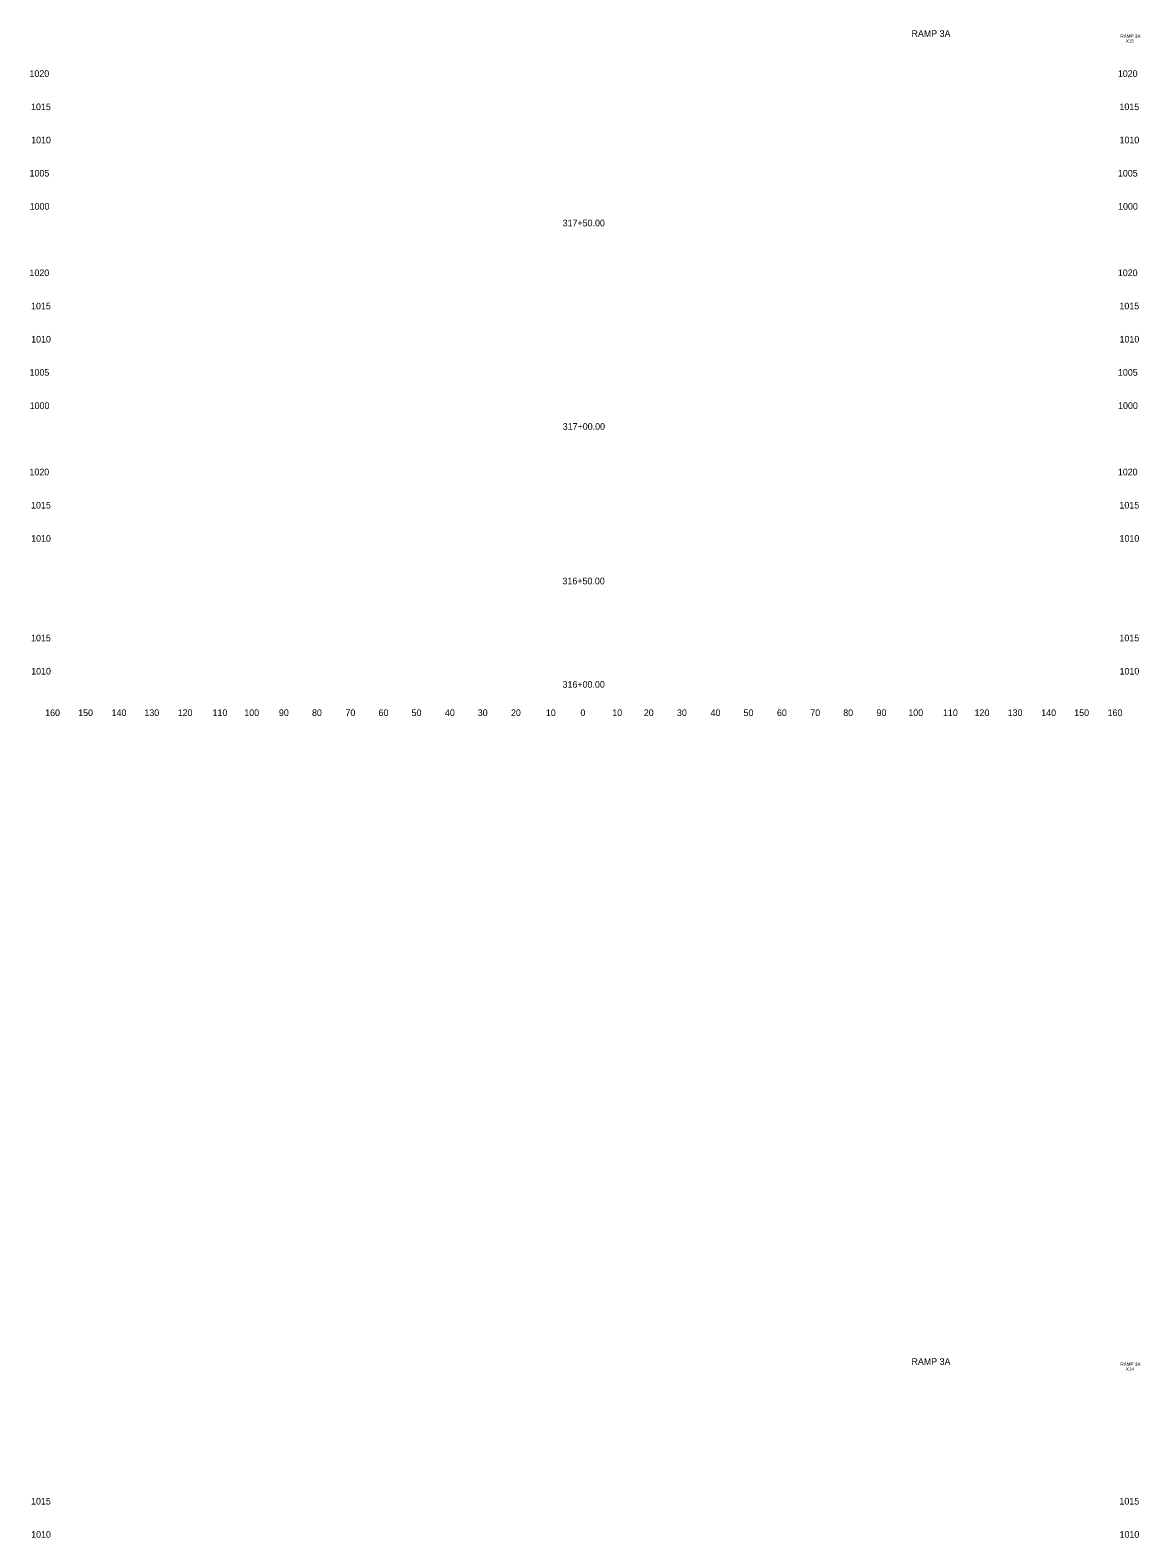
# Model space of a CAD drawing. Extents: x 4286 to 5843, y 4997 to 8804.
# Drawn here: x 5508.6 to 5842.8, y 6350 to 6804.1 of the extents above; entities that cross this region are included whole.
import ezdxf

# ---------------------------------------------------------------- set-up
doc = ezdxf.new("R2010")
doc.units = 0
for name, color, linetype in [('RD_SHT_ID', 7, 'Continuous'), ('RD_XS_TX_Offset', 7, 'Continuous'), ('RD_XS_TX_Station', 7, 'Continuous')]:
    doc.layers.add(name, color=color, linetype=linetype)

msp = doc.modelspace()

# ---------------------------------------------------------------- texts
at = {"layer": 'RD_SHT_ID'}
for s, height, p in [('RAMP 3A', 2, (5774.02, 6802.06)), ('RAMP 3A', 1, (5836.93, 6801.8)), ('X15', 1, (5838.57, 6800.3)), ('RAMP 3A', 2, (5774.02, 6402.06)), ('RAMP 3A', 1, (5836.93, 6401.8)), ('X14', 1, (5838.57, 6400.3))]:
    msp.add_text(s, height=height, dxfattribs=at).set_placement(p)
at = {"layer": 'RD_XS_TX_Offset'}
for s, p in [('1020', (5508.37, 6790)), ('1020', (5836.17, 6790)), ('1015', (5508.85, 6780)), ('1015', (5836.65, 6780)), ('1010', (5508.88, 6770)), ('1010', (5836.68, 6770)), ('1005', (5508.4, 6760)), ('1005', (5836.2, 6760)), ('1000', (5508.44, 6750)), ('1000', (5836.24, 6750)), ('1020', (5508.37, 6730)), ('1020', (5836.17, 6730)), ('1015', (5508.85, 6720)), ('1015', (5836.65, 6720)), ('1010', (5508.88, 6710)), ('1010', (5836.68, 6710)), ('1005', (5508.4, 6700)), ('1005', (5836.2, 6700)), ('1000', (5508.44, 6690)), ('1000', (5836.24, 6690)), ('1020', (5508.37, 6670)), ('1020', (5836.17, 6670)), ('1015', (5508.85, 6660)), ('1015', (5836.65, 6660)), ('1010', (5508.88, 6650)), ('1010', (5836.68, 6650)), ('1015', (5508.85, 6620)), ('1015', (5836.65, 6620)), ('1010', (5508.88, 6610)), ('1010', (5836.68, 6610)), ('160', (5513.1, 6597.5)), ('150', (5523.04, 6597.5)), ('140', (5533.1, 6597.5)), ('130', (5542.99, 6597.5)), ('120', (5553.01, 6597.5)), ('110', (5563.51, 6597.5)), ('100', (5573.07, 6597.5)), ('90', (5583.5, 6597.5)), ('80', (5593.46, 6597.5)), ('70', (5603.54, 6597.5)), ('60', (5613.5, 6597.5)), ('50', (5623.43, 6597.5)), ('40', (5633.5, 6597.5)), ('30', (5643.39, 6597.5)), ('20', (5653.4, 6597.5)), ('10', (5663.91, 6597.5)), ('0', (5674.3, 6597.5)), ('0', (5674.3, 6597.5)), ('10', (5683.91, 6597.5)), ('20', (5693.4, 6597.5)), ('30', (5703.39, 6597.5)), ('40', (5713.5, 6597.5)), ('50', (5723.43, 6597.5)), ('60', (5733.5, 6597.5)), ('70', (5743.54, 6597.5)), ('80', (5753.46, 6597.5)), ('90', (5763.5, 6597.5)), ('100', (5773.07, 6597.5)), ('110', (5783.51, 6597.5)), ('120', (5793.01, 6597.5)), ('130', (5802.99, 6597.5)), ('140', (5813.1, 6597.5)), ('150', (5823.04, 6597.5)), ('160', (5833.1, 6597.5)), ('1015', (5508.85, 6360)), ('1015', (5836.65, 6360)), ('1010', (5508.88, 6350)), ('1010', (5836.68, 6350))]:
    msp.add_text(s, height=2, dxfattribs=at).set_placement(p)
at = {"layer": 'RD_XS_TX_Station'}
for s, p in [('317+50.00', (5668.96, 6745.01)), ('317+00.00', (5668.99, 6683.72)), ('316+50.00', (5668.91, 6637.17)), ('316+00.00', (5668.94, 6606.02))]:
    msp.add_text(s, height=2, dxfattribs=at).set_placement(p)

doc.saveas('drawing.dxf')
